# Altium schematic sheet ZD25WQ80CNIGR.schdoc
size 127 x 101 mm
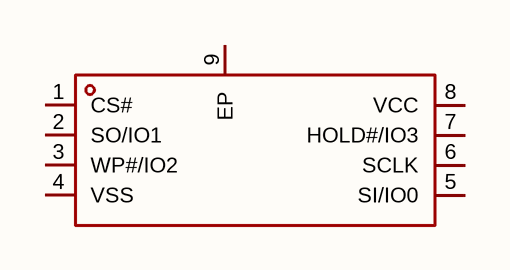
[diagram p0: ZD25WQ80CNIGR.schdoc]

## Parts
U?  zd25wq80cnigr  [USON-8_L1.5-W1.5-P0.40-BL-EP]  (value not drawn)

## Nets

Not connected (* = marked no-connect by the designer): U? 1(CS#) 2(SO/IO1) 3(WP#/IO2) 4(VSS) 5(SI/IO0) 6(SCLK) 7(HOLD#/IO3) 8(VCC) 9(EP)

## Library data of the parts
U? = zd25wq80cnigr: 接口类型:SPI;存储容量:8Mbit;时钟频率(fc):104MHz;; Manufacturer: Zetta(澜智); AddInBom: yes; ModelId: 5757cbfba7d0405e801eee9fb676df23; ModelName: USON-8_L1.5-W1.5-H0.5-P0.40-BL-EP; ModelTransform: 59.055,59.8424,0,180,0,0,0,0,0; Interface: SPI; Memory Size: 8Mbit; Clock Frequency: 104MHz; Voltage - Supply: 1.65V~3.6V; Standby Supply Current: 0.1uA; Program / Erase Cycles: 100000次; Page Programming Time (Tpp): 1.5ms; Block Erase Time(tBE): 6ms; Data Retention - TDR (Year): 20年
